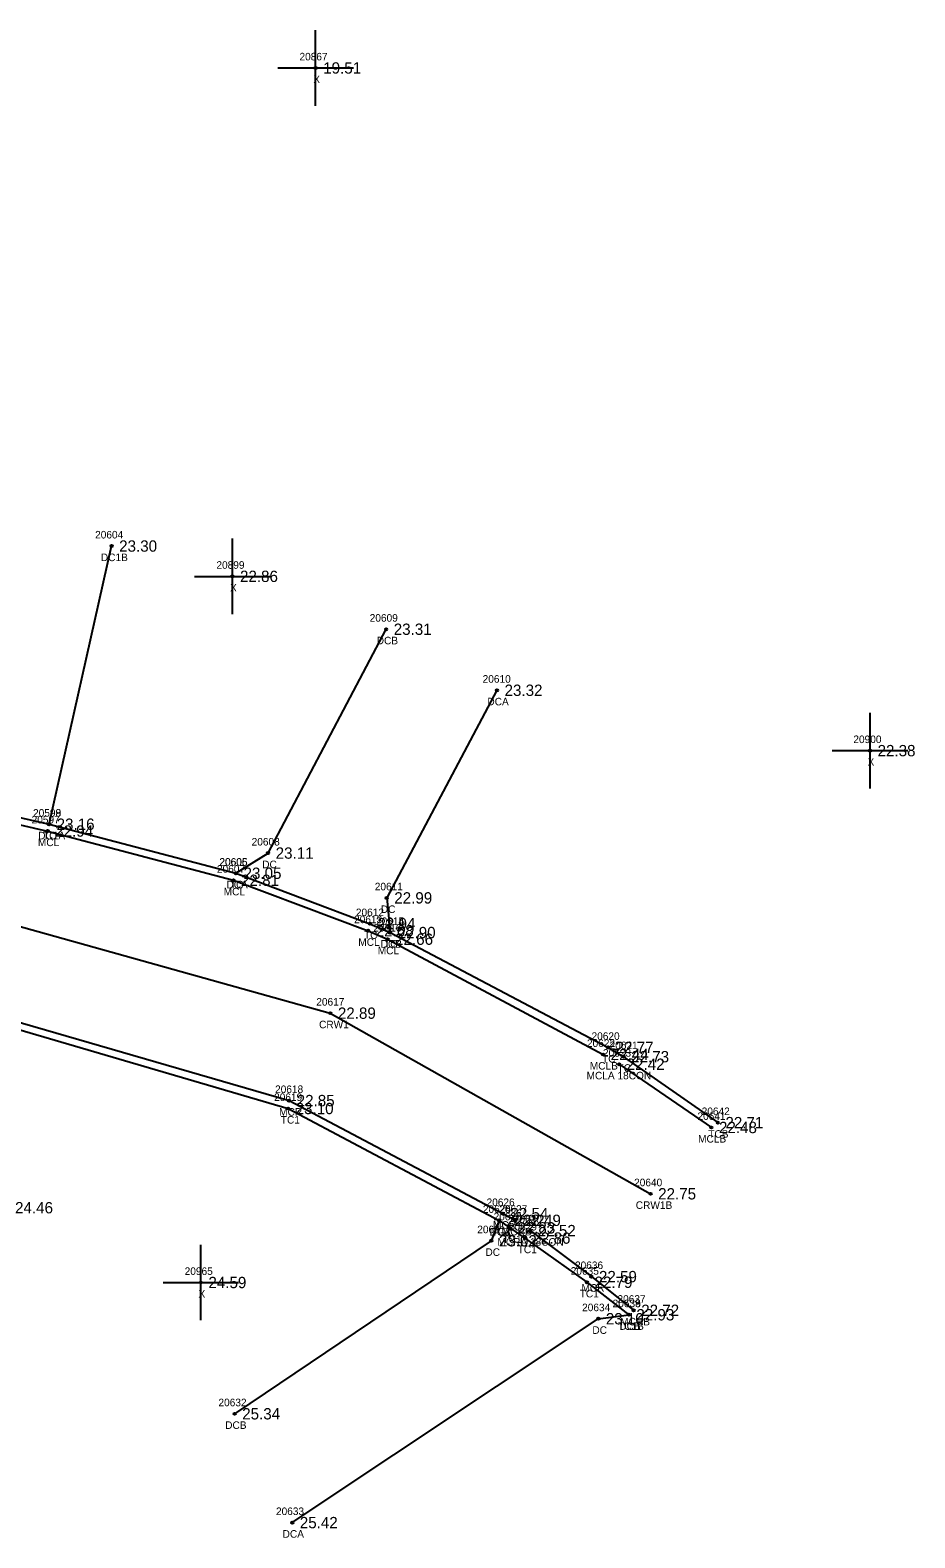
# Model space of a CAD drawing. Extents: x 2655177 to 2656219, y 761780 to 764748.
# Drawn here: x 2655710.1 to 2655827.2, y 762680.6 to 762880.1 of the extents above; entities that cross this region are included whole.
import ezdxf

# ---------------------------------------------------------------- set-up
doc = ezdxf.new("R2010")
doc.units = 0
for name, color, linetype in [('RD_DTM_BkLn1', 7, 'Continuous'), ('RD_DTM_BkLn2', 7, 'Continuous'), ('RD_EX_Conc', 7, 'Continuous'), ('RD_EX_Conc_txCode', 7, 'Continuous'), ('RD_EX_Misc', 7, 'Continuous'), ('RD_EX_Misc_txCode', 7, 'Continuous'), ('RD_EX_TX_Conc_ELEV', 7, 'Continuous'), ('RD_EX_TX_Misc_ELEV', 7, 'Continuous'), ('RD_HC_Survey_ELEV', 7, 'Continuous'), ('RD_HC_Survey_txCode', 7, 'Continuous'), ('RD_SMD_Locator', 7, 'Continuous')]:
    doc.layers.add(name, color=color, linetype=linetype)

msp = doc.modelspace()

# ---------------------------------------------------------------- linework, layer by layer
at = {"layer": 'RD_DTM_BkLn1'}
msp.add_lwpolyline([(2655621.78, 762781.91), (2655702.96, 762763.14), (2655749.84, 762750.03), (2655792.21, 762726.12)], dxfattribs=at)
at = {"layer": 'RD_DTM_BkLn2'}
for points in [[(2655647.95, 762795.55), (2655649.41, 762795.03), (2655656.99, 762789.66), (2655668.63, 762785.17), (2655695.58, 762778.92), (2655712.63, 762775.04), (2655737.36, 762768.55), (2655755.08, 762761.87), (2655757.75, 762760.7), (2655786.58, 762745.49), (2655788.64, 762744.27), (2655801.11, 762735.54)], [(2655638.83, 762758.42), (2655640.71, 762758.22), (2655649.02, 762759.63), (2655656.2, 762759.66), (2655662.94, 762758.71), (2655700.16, 762750.35), (2655744.25, 762737.41), (2655772.16, 762722.6), (2655773.58, 762721.61), (2655775.59, 762720.26), (2655783.79, 762714.41), (2655789.33, 762710.11)]]:
    msp.add_lwpolyline(points, dxfattribs=at)
at = {"layer": 'RD_EX_Conc'}
for p, q in [((2655712.63, 762775.04), (2655720.9, 762811.86)), ((2655788.05, 762743.27), (2655800.26, 762734.9))]:
    msp.add_line(p, q, dxfattribs=at)
for points in [[(2655737.36, 762768.55), (2655741.61, 762771.22), (2655757.23, 762800.85)], [(2655647.95, 762795.55), (2655656.5, 762788.85), (2655668.3, 762784.32), (2655695.43, 762778.05), (2655712.44, 762774.14), (2655737.03, 762767.62), (2655754.84, 762760.94), (2655757.41, 762759.82), (2655785.93, 762744.56)], [(2655771.89, 762792.77), (2655757.3, 762765.29), (2655757.75, 762760.7)], [(2655638.83, 762758.42), (2655640.65, 762759.07), (2655648.88, 762760.53), (2655656.27, 762760.57), (2655663.1, 762759.53), (2655700.27, 762751.26), (2655744.39, 762738.46), (2655772.67, 762723.5), (2655774.32, 762722.61)], [(2655772.16, 762722.6), (2655771.14, 762719.9), (2655737.18, 762697)], [(2655776.29, 762721.25), (2655784.38, 762715.16), (2655789.97, 762710.7)], [(2655744.8, 762682.6), (2655785.29, 762709.58), (2655789.33, 762710.11)]]:
    msp.add_lwpolyline(points, dxfattribs=at)
at = {"layer": 'RD_EX_Misc'}
for p, q in [((2655747.9, 762870.14), (2655747.9, 762880.14)), ((2655742.9, 762875.14), (2655752.9, 762875.14)), ((2655736.89, 762802.85), (2655736.89, 762812.85)), ((2655731.89, 762807.85), (2655741.89, 762807.85)), ((2655821.24, 762779.78), (2655821.24, 762789.78)), ((2655816.24, 762784.78), (2655826.24, 762784.78)), ((2655732.71, 762709.38), (2655732.71, 762719.38)), ((2655727.71, 762714.38), (2655737.71, 762714.38))]:
    msp.add_line(p, q, dxfattribs=at)
at = {"layer": 'RD_SMD_Locator'}
for centre in [(2655747.9, 762875.14), (2655720.9, 762811.86), (2655736.89, 762807.85), (2655757.23, 762800.85), (2655771.89, 762792.77), (2655821.24, 762784.78), (2655712.44, 762774.14), (2655712.63, 762775.04), (2655712.63, 762775.04), (2655741.61, 762771.22), (2655737.03, 762767.62), (2655737.36, 762768.55), (2655737.36, 762768.55), (2655757.3, 762765.29), (2655755.08, 762761.87), (2655754.84, 762760.94), (2655757.41, 762759.82), (2655757.75, 762760.7), (2655757.75, 762760.7), (2655749.84, 762750.03), (2655785.93, 762744.56), (2655786.58, 762745.49), (2655788.64, 762744.27), (2655788.05, 762743.27), (2655744.39, 762738.46), (2655744.25, 762737.41), (2655801.11, 762735.54), (2655800.26, 762734.9), (2655792.21, 762726.12), (2655772.16, 762722.6), (2655772.16, 762722.6), (2655772.67, 762723.5), (2655773.58, 762721.61), (2655774.32, 762722.61), (2655771.14, 762719.9), (2655775.59, 762720.26), (2655776.29, 762721.25), (2655732.71, 762714.38), (2655783.79, 762714.41), (2655784.38, 762715.16), (2655785.29, 762709.58), (2655789.33, 762710.11), (2655789.33, 762710.11), (2655789.97, 762710.7), (2655737.18, 762697), (2655744.8, 762682.6)]:
    msp.add_circle(centre, 0.15, dxfattribs=at)

# ---------------------------------------------------------------- texts
at = {"layer": 'RD_EX_Conc_txCode'}
for s, p in [('20604', (2655718.72, 762812.86)), ('DC1B', (2655719.48, 762809.86)), ('20609', (2655755.05, 762801.85)), ('DCB', (2655755.98, 762798.85)), ('20610', (2655769.99, 762793.77)), ('DCA', (2655770.62, 762790.77)), ('20597', (2655710.32, 762775.14)), ('20598', (2655710.51, 762776.04)), ('20599', (2655710.51, 762776.04)), ('DC1A', (2655711.19, 762773.04)), ('TC', (2655711.83, 762773.04)), ('MCL', (2655711.15, 762772.14)), ('20608', (2655739.43, 762772.22)), ('20607', (2655734.84, 762768.62)), ('20606', (2655735.15, 762769.55)), ('20605', (2655735.18, 762769.55)), ('DC', (2655740.83, 762769.22)), ('MCL', (2655735.73, 762765.62)), ('DCA', (2655736.09, 762766.55)), ('TC', (2655736.56, 762766.55)), ('20611', (2655755.72, 762766.29)), ('20612', (2655753.22, 762762.87)), ('DC', (2655756.52, 762763.29)), ('20613', (2655752.98, 762761.94)), ('20616', (2655755.53, 762760.82)), ('20614', (2655755.89, 762761.7)), ('20615', (2655755.89, 762761.7)), ('MCL', (2655753.54, 762758.94)), ('TC', (2655754.29, 762759.87)), ('DCB', (2655756.5, 762758.7)), ('TC', (2655756.95, 762758.7)), ('MCL', (2655756.12, 762757.82)), ('20622', (2655783.79, 762745.56)), ('20620', (2655784.4, 762746.49)), ('20621', (2655786.78, 762745.27)), ('TC', (2655785.79, 762743.49)), ('20623', (2655785.91, 762744.27)), ('MCLA 18CON', (2655783.74, 762741.27)), ('MCLB', (2655784.17, 762742.56)), ('TC', (2655787.84, 762742.27)), ('20618', (2655742.53, 762739.46)), ('20619', (2655742.4, 762738.41)), ('MCR', (2655743.07, 762736.46)), ('TC1', (2655743.29, 762735.41)), ('20641', (2655798.41, 762735.9)), ('20642', (2655798.97, 762736.54)), ('MCLB', (2655798.5, 762732.9)), ('TCB', (2655799.84, 762733.54)), ('20624', (2655770.02, 762723.6)), ('20625', (2655770.02, 762723.6)), ('20626', (2655770.51, 762724.5)), ('20627', (2655772.18, 762723.61)), ('20631', (2655769.28, 762720.9)), ('MCR', (2655771.36, 762721.5)), ('20628', (2655771.44, 762722.61)), ('20629', (2655773.45, 762721.26)), ('20630', (2655774.11, 762722.25)), ('DCA', (2655770.89, 762720.6)), ('TC1', (2655771.2, 762720.6)), ('MCRA 18CON', (2655771.95, 762719.25)), ('MCRB', (2655772.53, 762720.61)), ('TC1', (2655772.62, 762719.61)), ('DC', (2655770.36, 762717.9)), ('TC1', (2655774.63, 762718.26)), ('20635', (2655781.65, 762715.41)), ('20636', (2655782.21, 762716.16)), ('MCR', (2655783.07, 762713.16)), ('TC1', (2655782.83, 762712.41)), ('20638', (2655787.19, 762711.11)), ('20639', (2655787.19, 762711.11)), ('20637', (2655787.83, 762711.7)), ('20634', (2655783.15, 762710.58)), ('DC', (2655784.51, 762707.58)), ('TC1B', (2655787.9, 762708.11)), ('DCB', (2655788.08, 762708.11)), ('MCRB', (2655788.19, 762708.7)), ('20632', (2655735.04, 762698)), ('DCB', (2655735.93, 762695)), ('20633', (2655742.65, 762683.6)), ('DCA', (2655743.53, 762680.6))]:
    msp.add_text(s, height=1, dxfattribs=at).set_placement(p)
at = {"layer": 'RD_EX_Misc_txCode'}
for s, p in [('20867', (2655745.76, 762876.14)), ('X', (2655747.59, 762873.14)), ('20899', (2655734.77, 762808.85)), ('X', (2655736.57, 762805.85)), ('20900', (2655819.04, 762785.78)), ('X', (2655820.92, 762782.78)), ('20965', (2655730.57, 762715.38)), ('X', (2655732.4, 762712.38))]:
    msp.add_text(s, height=1, dxfattribs=at).set_placement(p)
at = {"layer": 'RD_EX_TX_Conc_ELEV'}
for s, p in [('23.30', (2655721.9, 762811.11)), ('23.31', (2655758.23, 762800.1)), ('23.32', (2655772.89, 762792.02)), ('23.16', (2655713.63, 762774.29)), ('23.16', (2655713.63, 762774.29)), ('22.94', (2655713.44, 762773.39)), ('23.11', (2655742.61, 762770.47)), ('22.81', (2655738.03, 762766.87)), ('23.05', (2655738.36, 762767.8)), ('23.05', (2655738.36, 762767.8)), ('22.99', (2655758.3, 762764.54)), ('22.68', (2655755.84, 762760.19)), ('22.94', (2655756.08, 762761.12)), ('22.66', (2655758.41, 762759.07)), ('22.90', (2655758.75, 762759.95)), ('22.90', (2655758.75, 762759.95)), ('22.77', (2655787.58, 762744.74)), ('22.44', (2655786.93, 762743.81)), ('22.42', (2655789.05, 762742.52)), ('22.73', (2655789.64, 762743.52)), ('23.10', (2655745.25, 762736.66)), ('22.85', (2655745.39, 762737.71)), ('22.48', (2655801.26, 762734.15)), ('22.71', (2655802.11, 762734.79)), ('22.54', (2655773.67, 762722.75)), ('22.82', (2655773.16, 762721.85)), ('22.82', (2655773.16, 762721.85)), ('22.83', (2655774.58, 762720.86)), ('22.49', (2655775.32, 762721.86)), ('22.52', (2655777.29, 762720.5)), ('23.02', (2655772.14, 762719.15)), ('22.86', (2655776.59, 762719.51)), ('22.59', (2655785.38, 762714.41)), ('22.79', (2655784.79, 762713.66)), ('23.10', (2655786.29, 762708.83)), ('22.93', (2655790.33, 762709.36)), ('22.93', (2655790.33, 762709.36)), ('22.72', (2655790.97, 762709.95)), ('25.34', (2655738.18, 762696.25)), ('25.42', (2655745.8, 762681.85))]:
    msp.add_text(s, height=1.5, dxfattribs=at).set_placement(p)
at = {"layer": 'RD_EX_TX_Misc_ELEV'}
for s, p in [('19.51', (2655748.9, 762874.39)), ('22.86', (2655737.89, 762807.1)), ('22.38', (2655822.24, 762784.03)), ('24.46', (2655708.13, 762723.53)), ('24.59', (2655733.71, 762713.63))]:
    msp.add_text(s, height=1.5, dxfattribs=at).set_placement(p)
at = {"layer": 'RD_HC_Survey_ELEV'}
for s, p in [('22.89', (2655750.84, 762749.28)), ('22.75', (2655793.21, 762725.37))]:
    msp.add_text(s, height=1.5, dxfattribs=at).set_placement(p)
at = {"layer": 'RD_HC_Survey_txCode'}
for s, p in [('20617', (2655747.98, 762751.03)), ('CRW1', (2655748.35, 762748.03)), ('20640', (2655790.03, 762727.12)), ('CRW1B', (2655790.25, 762724.12))]:
    msp.add_text(s, height=1, dxfattribs=at).set_placement(p)

doc.saveas('drawing.dxf')
